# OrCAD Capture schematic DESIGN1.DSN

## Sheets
1 PAGE2: size Custom
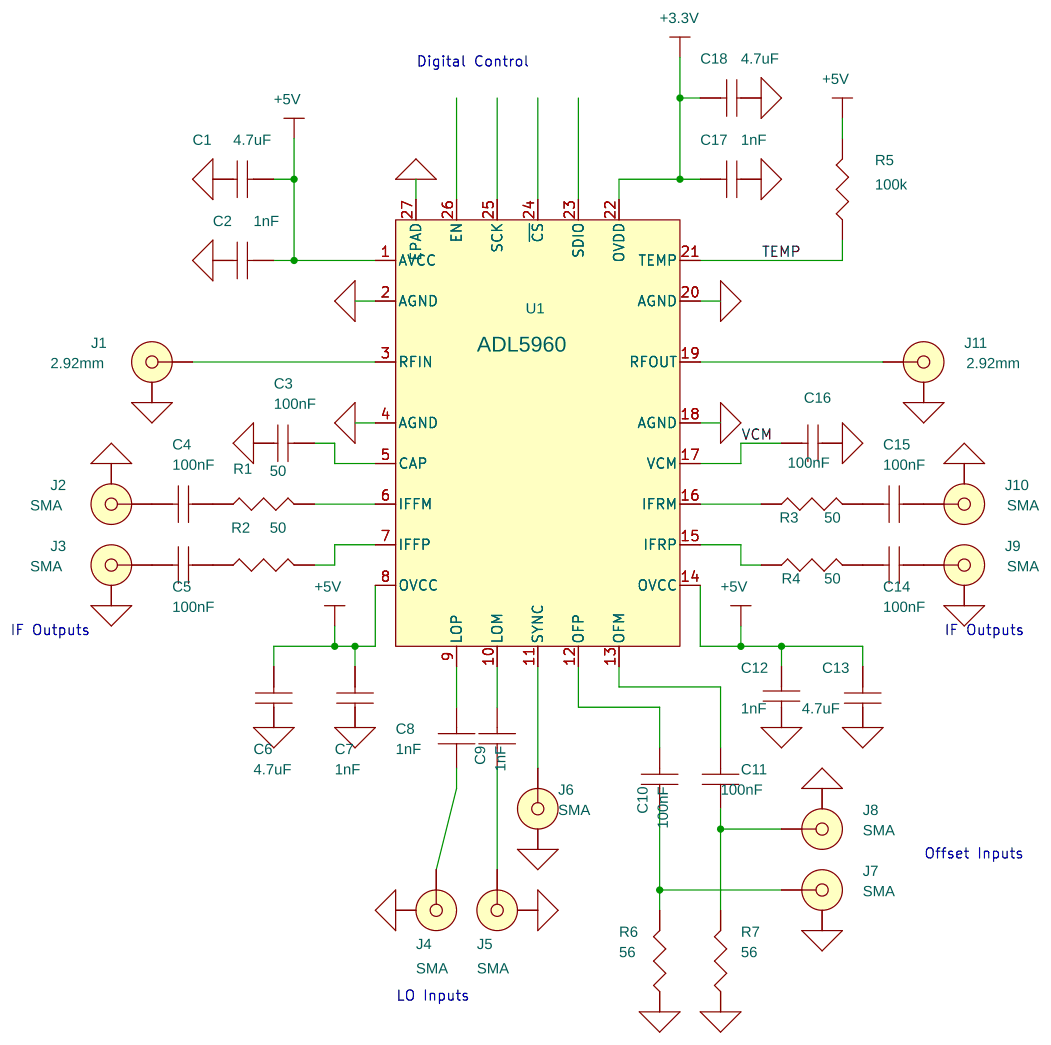
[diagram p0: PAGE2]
2 PAGE1: size A
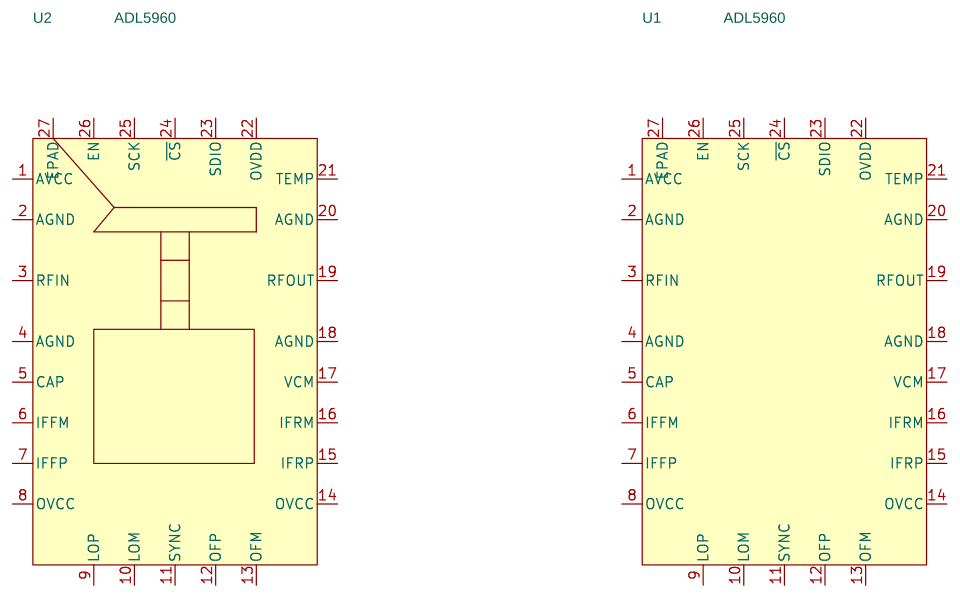
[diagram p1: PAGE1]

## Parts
sheet PAGE1
U2  ADL5960
sheet PAGE2
C1  4.7uF
C2  1nF
C3  100nF
C4  100nF
C5  100nF
C6  4.7uF
C7  1nF
C8  1nF
C9  1nF
C10  100nF
C11  100nF
C12  1nF
C13  4.7uF
C14  100nF
C15  100nF
C16  100nF
C17  1nF
C18  4.7uF
J1  2.92mm
J2  SMA
J3  SMA
J4  SMA
J5  SMA
J6  SMA
J7  SMA
J8  SMA
J9  SMA
J10  SMA
J11  2.92mm
R1  50
R2  50
R3  50
R4  50
R5  100k
R6  56
R7  56
U1  ADL5960
U1#2  ADL5960

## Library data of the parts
U2 = 126ANS_10
C1-C18 = CAPACITOR_NON-POL
J1-J5 J7-J11 = BNC_1
J6 = BNC_2
R1-R7 = R
U1 U1#2 = 126ANS_8

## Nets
+3.3V: C17.2 C18.2 U1#2.22(OVDD)
+5V: C1.2 C2.2 C6.2 C7.2 C12.1 C13.2 R5.2 U1#2.1(AVCC) U1#2.8(OVCC) U1#2.14(OVCC)
GND_SIGNAL: C1.1 C2.1 C3.1 C6.1 C7.1 C12.2 C13.1 C16.1 C17.1 C18.1 J1.2(SHIELD) J2.2(SHIELD) J3.2(SHIELD) J4.2(SHIELD) J5.2(SHIELD) J6.2(SHIELD) J7.2(SHIELD) J8.2(SHIELD) J9.2(SHIELD) J10.2(SHIELD) J11.2(SHIELD) R6.1 R7.1 U1#2.2(AGND) U1#2.4(AGND) U1#2.18(AGND) U1#2.20(AGND) U1#2.27(EPAD)
TEMP: R5.1 U1#2.21(TEMP)
VCM: C16.2 U1#2.17(VCM)
N03955: J1.1(CENTER) U1#2.3(RFIN)
N03957: J11.1(CENTER) U1#2.19(RFOUT)
N03977: R1.2 U1#2.6(IFFM)
N03979: R2.2 U1#2.7(IFFP)
N03985: R3.1 U1#2.16(IFRM)
N03987: R4.1 U1#2.15(IFRP)
N03993: C3.2 U1#2.5(CAP)
N06025: C8.2 U1#2.9(LOP)
N06029: C9.2 U1#2.10(LOM)
N06033: C8.1 J4.1(CENTER)
N06249: C9.1 J5.1(CENTER)
N06304: C10.2 U1#2.12(OFP)
N06308: C11.2 U1#2.13(OFM)
N06621: J6.1(CENTER) U1#2.11(SYNC)
N10079: C10.1 J7.1(CENTER) R6.2
N10083: C11.1 J8.1(CENTER) R7.2
N15830: C4.1 R1.1
N15836: C15.2 R3.2
N15840: C15.1 J10.1(CENTER)
N15842: C5.1 R2.1
N15843: C14.2 R4.2
N15845: C14.1 J9.1(CENTER)
N15847: C4.2 J2.1(CENTER)
N15848: C5.2 J3.1(CENTER)

Not connected (* = marked no-connect by the designer): U1 1(AVCC) 2(AGND) 3(RFIN) 4(AGND) 5(CAP) 6(IFFM) 7(IFFP) 8(OVCC) 9(LOP) 10(LOM) 11(SYNC) 12(OFP) 13(OFM) 14(OVCC) 15(IFRP) 16(IFRM) 17(VCM) 18(AGND) 19(RFOUT) 20(AGND) 21(TEMP) 22(OVDD) 23(SDIO) 24(~{CS}) 25(SCK) 26(EN) 27(EPAD); U1#2 23(SDIO) 24(~{CS}) 25(SCK) 26(EN); U2 1(AVCC) 2(AGND) 3(RFIN) 4(AGND) 5(CAP) 6(IFFM) 7(IFFP) 8(OVCC) 9(LOP) 10(LOM) 11(SYNC) 12(OFP) 13(OFM) 14(OVCC) 15(IFRP) 16(IFRM) 17(VCM) 18(AGND) 19(RFOUT) 20(AGND) 21(TEMP) 22(OVDD) 23(SDIO) 24(~{CS}) 25(SCK) 26(EN) 27(EPAD)

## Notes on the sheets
sheet 1
- Digital Control
- IF Outputs
- IF Outputs
- Offset Inputs
- LO Inputs
